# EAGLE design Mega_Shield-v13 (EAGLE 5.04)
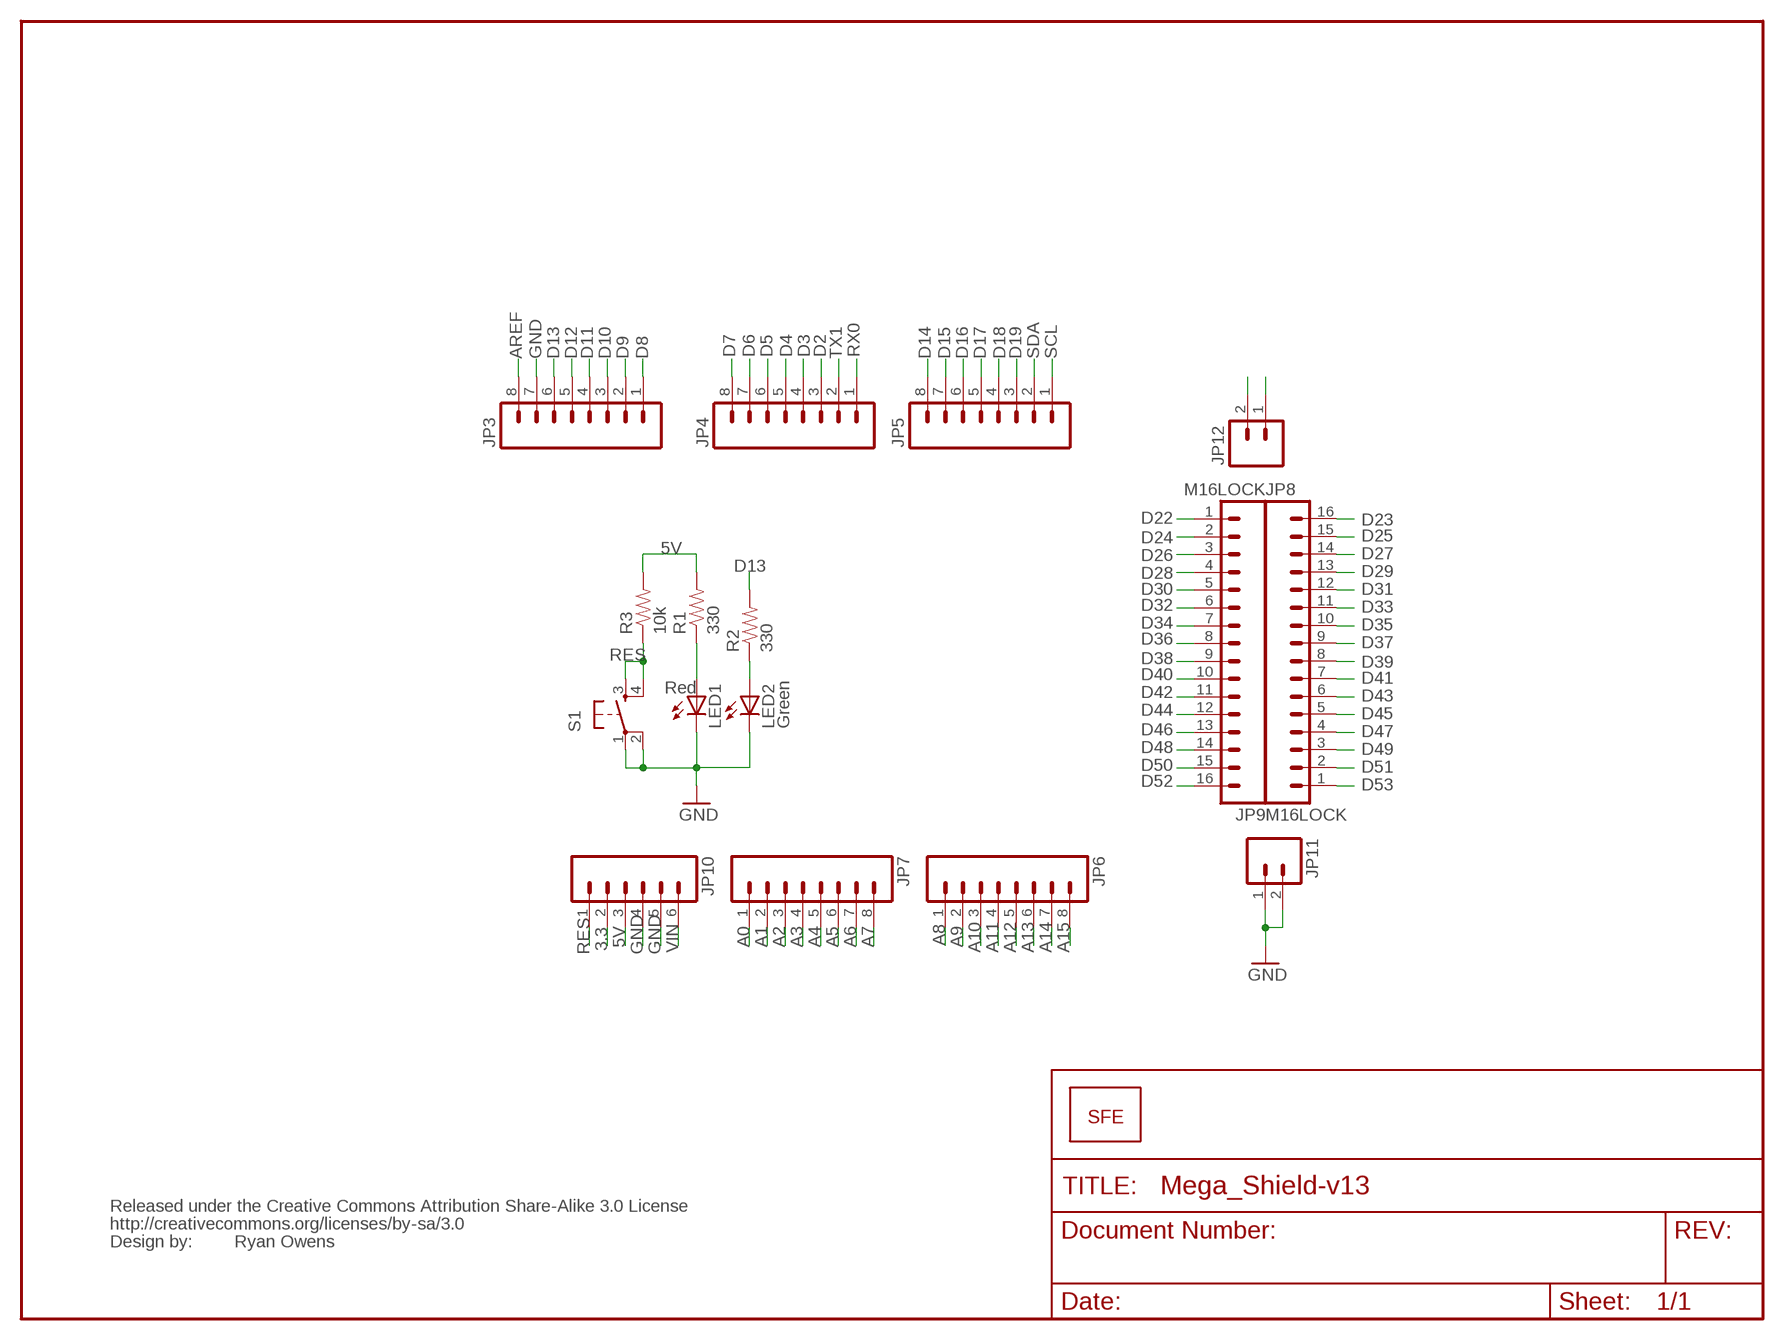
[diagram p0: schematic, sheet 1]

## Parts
JP3  M08LOCK  [1X08_LOCK]
JP4  M08LOCK  [1X08_LOCK]
JP5  M08LOCK  [1X08_LOCK]
JP6  M08LOCK  [1X08_LOCK]
JP7  M08LOCK  [1X08_LOCK]
JP8  M16LOCK  [1X16_LOCK]
JP9  M16LOCK  [1X16_LOCK]
JP10  M06LOCK  [1X06_LOCK]
JP11  M02LOCK  [1X02_LOCK]
JP12  M02LOCK  [1X02_LOCK]
LED1  Red  LED5MM  [LED5MM]
LED2  Green  LED5MM  [LED5MM]
R1  330  RESISTORPTH1  [AXIAL-0.3]
R2  330  RESISTORPTH1  [AXIAL-0.3]
R3  10k  RESISTORPTH1  [AXIAL-0.3]
S1  TAC_SWITCHPTH  [TACTILE-PTH]
U$1  LOGO-SFENEW  [SFE-NEW-WEBLOGO]
U$2  CREATIVE_COMMONS  [CREATIVE_COMMONS]

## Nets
3.3: JP10.2
5V: JP10.3 R1.P$2 R3.P$2
5V@1: JP12.1 JP12.2
A0: JP7.1
A1: JP7.2
A2: JP7.3
A3: JP7.4
A4: JP7.5
A5: JP7.6
A6: JP7.7
A7: JP7.8
A8: JP6.1
A9: JP6.2
A10: JP6.3
A11: JP6.4
A12: JP6.5
A13: JP6.6
A14: JP6.7
A15: JP6.8
AREF: JP3.8
D2: JP4.3
D3: JP4.4
D4: JP4.5
D5: JP4.6
D6: JP4.7
D7: JP4.8
D8: JP3.1
D9: JP3.2
D10: JP3.3
D11: JP3.4
D12: JP3.5
D13: JP3.6 R2.P$2
D14: JP5.8
D15: JP5.7
D16: JP5.6
D17: JP5.5
D18: JP5.4
D19: JP5.3
D22: JP9.1
D23: JP8.16
D24: JP9.2
D25: JP8.15
D26: JP9.3
D27: JP8.14
D28: JP9.4
D29: JP8.13
D30: JP9.5
D31: JP8.12
D32: JP9.6
D33: JP8.11
D34: JP9.7
D35: JP8.10
D36: JP9.8
D37: JP8.9
D38: JP9.9
D39: JP8.8
D40: JP9.10
D41: JP8.7
D42: JP9.11
D43: JP8.6
D44: JP9.12
D45: JP8.5
D46: JP9.13
D47: JP8.4
D48: JP9.14
D49: JP8.3
D50: JP9.15
D51: JP8.2
D52: JP9.16
D53: JP8.1
GND: JP3.7 JP10.4 JP10.5 JP11.1 JP11.2 LED1.K(C) LED2.K(C) S1.1 S1.2
N$126: LED1.A R1.P$1
N$127: LED2.A R2.P$1
RES: JP10.1 R3.P$1 S1.3 S1.4
RX0: JP4.1
SCL: JP5.1
SDA: JP5.2
TX1: JP4.2
VIN: JP10.6

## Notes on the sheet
- Ryan Owens

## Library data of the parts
JP3-JP7 = SparkFun:M08: Header 8 Standard 8-pin 0.1" header. Use with straight break away headers (SKU : PRT-00116), right angle break away headers (PRT-00553), swiss pins (PRT-00743), machine pins (PRT-00117), and female headers (PRT-00115).
JP8 JP9 = SparkFun:M16
JP10 = SparkFun:M06: Header 6 Standard 6-pin 0.1" header. Use with straight break away headers (SKU : PRT-00116), right angle break away headers (PRT-00553), swiss pins (PRT-00743), machine pins (PRT-00117), and female headers (PRT-00115). Molex polarized connector foot print use with SKU : PRT-08094 with associated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
JP11 JP12 = SparkFun:M02: Header 2
LED1 LED2 = SparkFun:LED: LEDs
R1-R3 = SparkFun:RESISTOR: Resistor
S1 = SparkFun:TAC_SWITCH: Momentary Switch Button commonly used for reset or general input. Spark Fun Electronics SKU : COM-00097
U$1 = SparkFun:LOGO-SFE: Spark Fun Electronics PCB Logo
U$2 = SparkFun:CREATIVE_COMMONS

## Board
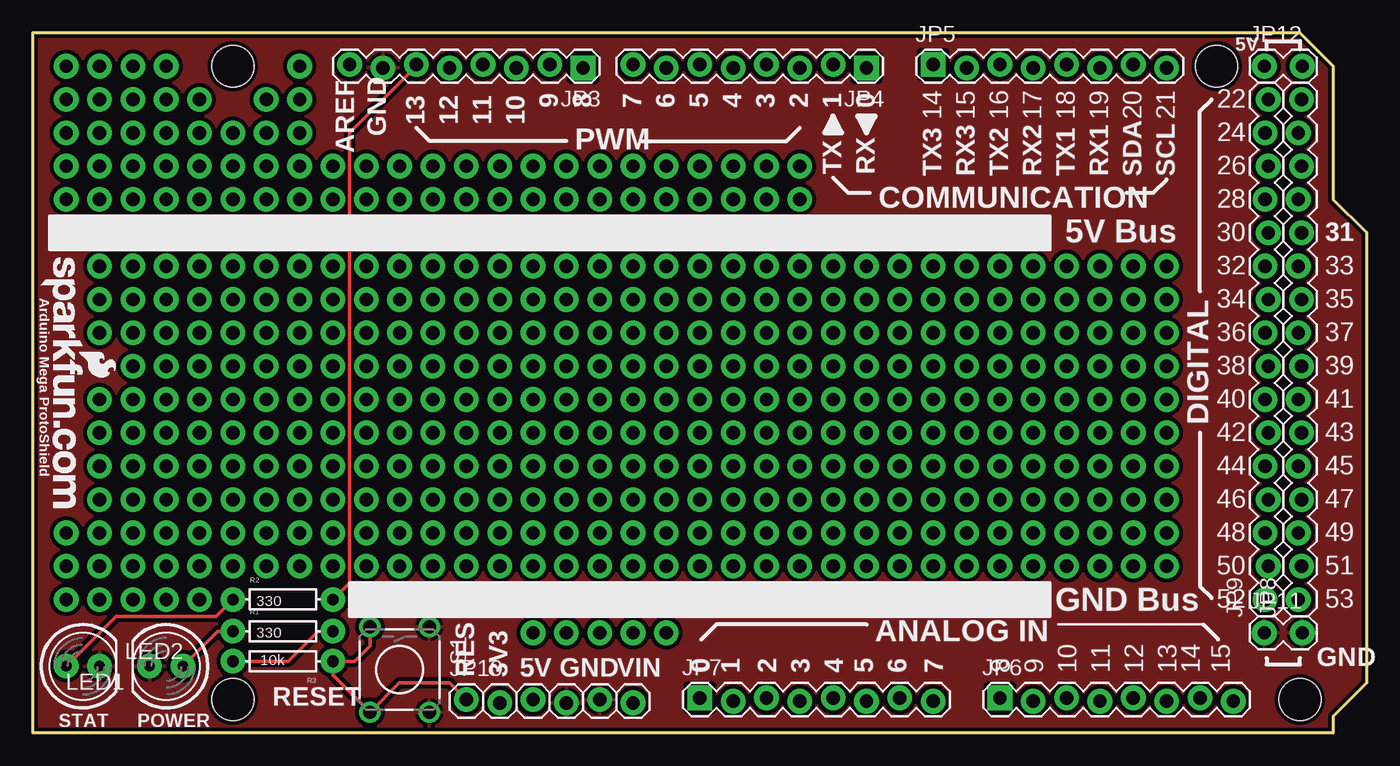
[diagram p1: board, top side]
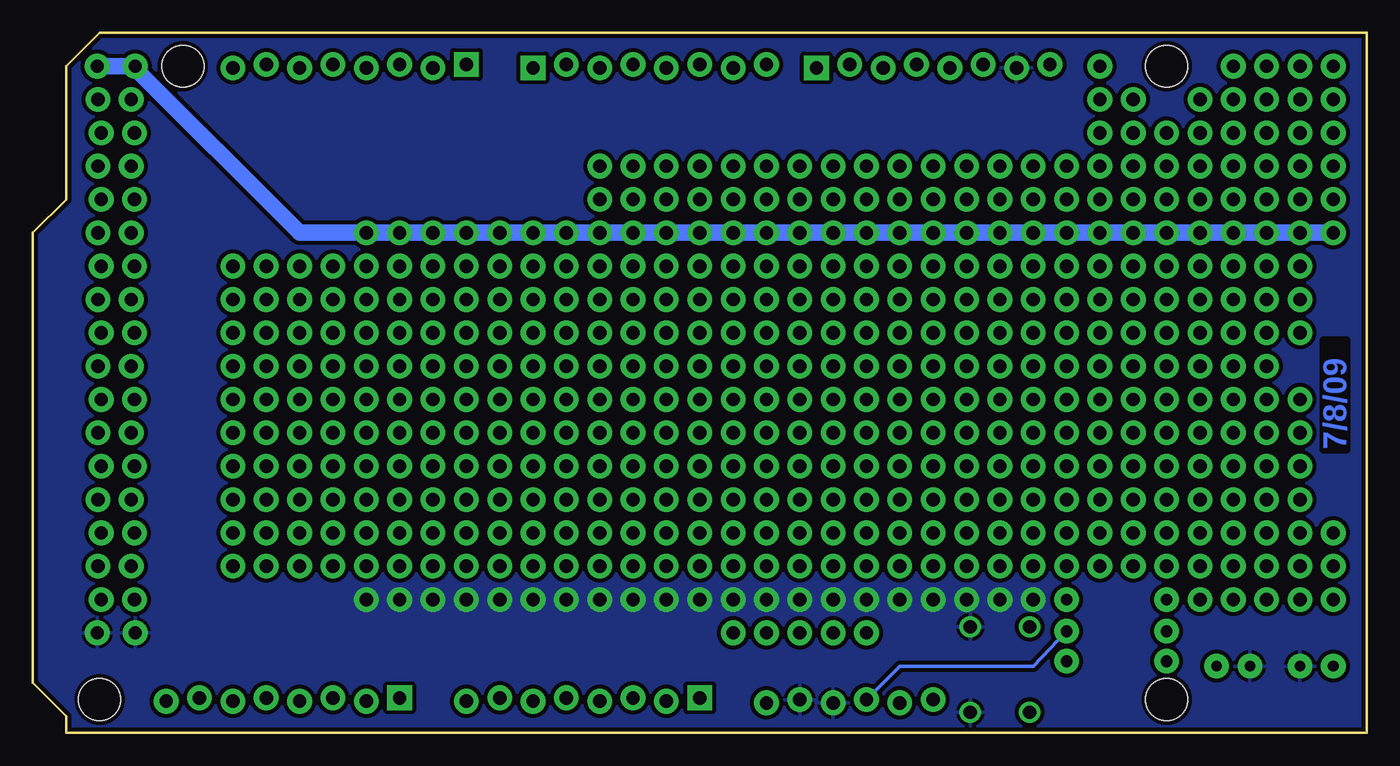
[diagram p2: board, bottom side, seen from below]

Size 101.6 x 53.34 mm. Coordinates in mm from the lower left corner, seen from the top.
Outline: 0,0 99.06,0 99.06,1.27 101.6,3.81 101.6,38.1 99.06,40.64 99.06,50.8 96.52,53.34 0,53.34 0,0
Copper layers (1*16): Top 0.035mm / dielectric 1.5mm / Bottom 0.035mm
Design rules "SparkFun": minimum track width 8mil, minimum drill 20mil, track to track 8mil, track to pad 8mil, pad to pad 8mil, via to via 8mil, smd to smd 8mil, copper to edge 10mil, drill to drill 8mil, minimum pad ring 12mil, minimum via ring 10mil, stop-mask expansion 4mil, vias tented up to drill 25mil, thermal gap 10mil
Holes 3.2 mm at 15.24,50.8 15.24,2.54 90.17,50.8 96.52,2.54

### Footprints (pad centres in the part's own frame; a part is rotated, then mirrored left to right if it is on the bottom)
1X08_LOCK = drill 1.016 pad 1.88 square: 1 0,0.127 | drill 1.016 pad 1.88 round: 2 2.54,-0.127; 3 5.08,0.127; 4 7.62,-0.127; 5 10.16,0.127; 6 12.7,-0.127; 7 15.24,0.127; 8 17.78,-0.127
1X16_LOCK = drill 1.016 pad 1.88 round: 1 0,0.127; 2 2.54,-0.127; 3 5.08,0.127; 4 7.62,-0.127; 5 10.16,0.127; 6 12.7,-0.127; 7 15.24,0.127; 8 17.78,-0.127; 9 20.32,0.127; 10 22.86,-0.127; 11 25.4,0.127; 12 27.94,-0.127; 13 30.48,0.127; 14 33.02,-0.127; 15 35.56,0.127; 16 38.1,-0.127
1X06_LOCK = drill 1.016 pad 1.88 round: 1 0,0; 2 2.54,-0.254; 3 5.08,0; 4 7.62,-0.254; 5 10.16,0; 6 12.7,-0.254
1X02_LOCK = drill 1.016 pad 1.88 round: 1 -0.178,0; 2 2.718,0
LED5MM = drill 0.813 pad 1.88 round: A -1.27,0; K 1.27,0
AXIAL-0.3 = drill 0.9 pad 1.88 round: P$1 -3.81,0; P$2 3.81,0
TACTILE-PTH = drill 1.016 round: 1 -3.251,2.261; 2 3.251,2.261; 3 -3.251,-2.261; 4 3.251,-2.261

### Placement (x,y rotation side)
JP3  41.91,50.8 180 top
JP4  63.5,50.8 180 top
JP5  68.58,50.8 0 top
JP6  73.66,2.54 0 top
JP7  50.8,2.54 0 top
JP8  96.52,10.16 90 top
JP9  93.98,10.16 90 top
JP10  33.02,2.54 0 top
JP11  93.98,7.62 0 top
JP12  93.98,50.8 0 top
LED1  10.16,5.08 180 top
LED2  3.81,5.08 0 top
R1  19.05,7.75 0 top
R2  19.05,10.16 0 top
R3  19.05,5.46 180 top
S1  27.94,4.83 270 top
U$1  0.64,36.2 270 top
U$2  not placed on the board

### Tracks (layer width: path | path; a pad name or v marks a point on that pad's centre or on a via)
3.3
  Top 0.203: JP10.2 35.56,2.54 JP10.2
5V
  Top 0.254: R3.P$2 19.43,5.46 21.72,7.75 R1.P$2
  Bottom 0.254: R1.P$2 25.4,5.08 35.56,5.08 JP10.3
5V@1  (via drill 1.02 pad 1.88)
  Bottom 1.27: v2.54,38.1 v5.08,38.1 v7.62,38.1 v10.16,38.1 v12.7,38.1 v15.24,38.1 v17.78,38.1 v20.32,38.1 v22.86,38.1 v25.4,38.1 v27.94,38.1 v30.48,38.1 v33.02,38.1 v35.56,38.1 v38.1,38.1 v40.64,38.1 v43.18,38.1 v45.72,38.1 v48.26,38.1 v50.8,38.1 v53.34,38.1 v55.88,38.1 v58.42,38.1 v60.96,38.1 v63.5,38.1 v66.04,38.1 v68.58,38.1 v71.12,38.1 v73.66,38.1 v76.2,38.1 81.1,38.1 81.28,38.1 93.98,50.8 JP12.1 96.52,50.8 JP12.2
A0
  Top 0.203: JP7.1 50.8,2.54
A1
  Top 0.203: JP7.2 53.34,2.54 JP7.2
A2
  Top 0.203: JP7.3 55.88,2.54
A3
  Top 0.203: JP7.4 58.42,2.54 JP7.4
A4
  Top 0.203: JP7.5 60.96,2.54
A5
  Top 0.203: JP7.6 63.5,2.54 JP7.6
A6
  Top 0.203: JP7.7 66.04,2.54
A7
  Top 0.203: JP7.8 68.58,2.54 JP7.8
A8
  Top 0.203: JP6.1 73.66,2.54
A9
  Top 0.203: JP6.2 76.2,2.54 JP6.2
A10
  Top 0.203: JP6.3 78.74,2.54
A11
  Top 0.203: JP6.4 81.28,2.54 JP6.4
A12
  Top 0.203: JP6.5 83.82,2.54
A13
  Top 0.203: JP6.6 86.36,2.54 JP6.6
A14
  Top 0.203: JP6.7 88.9,2.54
A15
  Top 0.203: JP6.8 91.44,2.54 JP6.8
AREF
  Top 0.203: JP3.8 24.13,50.8 JP3.8
D2
  Top 0.203: JP4.3 58.42,50.8
D3
  Top 0.203: JP4.4 55.88,50.8 JP4.4
D4
  Top 0.203: JP4.5 53.34,50.8
D5
  Top 0.203: JP4.6 50.8,50.8 JP4.6
D6
  Top 0.203: JP4.7 48.26,50.8
D7
  Top 0.203: JP4.8 45.72,50.8 JP4.8
D8
  Top 0.203: JP3.1 41.91,50.8
D9
  Top 0.203: JP3.2 39.37,50.8 JP3.2
D10
  Top 0.203: JP3.3 36.83,50.8
D11
  Top 0.203: JP3.4 34.29,50.8 JP3.4
D12
  Top 0.203: JP3.5 31.75,50.8
D13
  Top 0.254: R2.P$2 24.13,11.43 24.13,12.7 24.13,45.72 29.21,50.8 JP3.6
D14
  Top 0.203: JP5.8 86.36,50.8
D15
  Top 0.203: JP5.7 83.82,50.8 JP5.7
D16
  Top 0.203: JP5.6 81.28,50.8
D17
  Top 0.203: JP5.5 78.74,50.8 JP5.5
D18
  Top 0.203: JP5.4 76.2,50.8
D19
  Top 0.203: JP5.3 73.66,50.8 JP5.3
GND  (via drill 1.02 pad 1.88)
  other vias: 76.2,10.16 73.66,10.16 71.12,10.16 68.58,10.16 66.04,10.16 63.5,10.16 60.96,10.16 58.42,10.16 55.88,10.16 53.34,10.16 50.8,10.16 48.26,10.16 45.72,10.16 43.18,10.16 40.64,10.16 38.1,10.16 35.56,10.16 33.02,10.16 25.4,10.16 27.94,10.16 30.48,10.16
  pour Bottom (isolate 0.305): 0,0 99.06,0 99.06,1.27 101.6,3.81 101.6,38.1 99.06,40.64 99.06,50.8 96.52,53.34 0,53.34 0,2.54
  pour Top (isolate 0.305): 0,0 99.06,0 99.06,1.27 101.6,3.81 101.6,38.1 99.06,40.64 99.06,50.8 96.52,53.34 0,53.34 0,2.54
N$1  (via drill 1.02 pad 1.88)
  other vias: 27.94,12.7
N$2  (via drill 1.02 pad 1.88)
  other vias: 86.36,35.56
N$3  (via drill 1.02 pad 1.88)
  other vias: 86.36,33.02
N$4  (via drill 1.02 pad 1.88)
  other vias: 86.36,30.48
N$5  (via drill 1.02 pad 1.88)
  other vias: 86.36,27.94
N$6  (via drill 1.02 pad 1.88)
  other vias: 86.36,25.4
N$7  (via drill 1.02 pad 1.88)
  other vias: 86.36,22.86
N$8  (via drill 1.02 pad 1.88)
  other vias: 86.36,20.32
N$9  (via drill 1.02 pad 1.88)
  other vias: 86.36,17.78
N$10  (via drill 1.02 pad 1.88)
  other vias: 86.36,15.24
N$11  (via drill 1.02 pad 1.88)
  other vias: 86.36,12.7
N$12  (via drill 1.02 pad 1.88)
  other vias: 30.48,12.7
N$13  (via drill 1.02 pad 1.88)
  other vias: 2.54,10.16
N$14  (via drill 1.02 pad 1.88)
  other vias: 83.82,35.56
N$15  (via drill 1.02 pad 1.88)
  other vias: 83.82,33.02
N$16  (via drill 1.02 pad 1.88)
  other vias: 83.82,30.48
N$17  (via drill 1.02 pad 1.88)
  other vias: 83.82,27.94
N$18  (via drill 1.02 pad 1.88)
  other vias: 83.82,25.4
N$19  (via drill 1.02 pad 1.88)
  other vias: 83.82,22.86
N$20  (via drill 1.02 pad 1.88)
  other vias: 83.82,20.32
N$21  (via drill 1.02 pad 1.88)
  other vias: 83.82,17.78
N$22  (via drill 1.02 pad 1.88)
  other vias: 83.82,15.24
N$23  (via drill 1.02 pad 1.88)
  other vias: 83.82,12.7
N$24  (via drill 1.02 pad 1.88)
  other vias: 5.08,10.16
N$25  (via drill 1.02 pad 1.88)
  other vias: 7.62,10.16
N$26  (via drill 1.02 pad 1.88)
  other vias: 81.28,12.7
N$27  (via drill 1.02 pad 1.88)
  other vias: 81.28,15.24
N$28  (via drill 1.02 pad 1.88)
  other vias: 81.28,17.78
N$29  (via drill 1.02 pad 1.88)
  other vias: 81.28,20.32
N$30  (via drill 1.02 pad 1.88)
  other vias: 81.28,22.86
N$31  (via drill 1.02 pad 1.88)
  other vias: 81.28,25.4
N$32  (via drill 1.02 pad 1.88)
  other vias: 81.28,27.94
N$33  (via drill 1.02 pad 1.88)
  other vias: 81.28,30.48
N$34  (via drill 1.02 pad 1.88)
  other vias: 81.28,33.02
N$35  (via drill 1.02 pad 1.88)
  other vias: 81.28,35.56
N$36  (via drill 1.02 pad 1.88)
  other vias: 10.16,10.16
N$37  (via drill 1.02 pad 1.88)
  other vias: 12.7,10.16
N$38  (via drill 1.02 pad 1.88)
  other vias: 78.74,35.56
N$39  (via drill 1.02 pad 1.88)
  other vias: 78.74,33.02
N$40  (via drill 1.02 pad 1.88)
  other vias: 78.74,30.48
N$41  (via drill 1.02 pad 1.88)
  other vias: 78.74,27.94
N$42  (via drill 1.02 pad 1.88)
  other vias: 78.74,25.4
N$43  (via drill 1.02 pad 1.88)
  other vias: 78.74,22.86
N$44  (via drill 1.02 pad 1.88)
  other vias: 78.74,20.32
N$45  (via drill 1.02 pad 1.88)
  other vias: 78.74,17.78
N$46  (via drill 1.02 pad 1.88)
  other vias: 78.74,15.24
N$47  (via drill 1.02 pad 1.88)
  other vias: 78.74,12.7
N$50  (via drill 1.02 pad 1.88)
  other vias: 76.2,12.7
N$51  (via drill 1.02 pad 1.88)
  other vias: 76.2,15.24
N$52  (via drill 1.02 pad 1.88)
  other vias: 76.2,17.78
N$53  (via drill 1.02 pad 1.88)
  other vias: 76.2,20.32
N$54  (via drill 1.02 pad 1.88)
  other vias: 76.2,22.86
N$55  (via drill 1.02 pad 1.88)
  other vias: 76.2,25.4
N$56  (via drill 1.02 pad 1.88)
  other vias: 76.2,27.94
N$57  (via drill 1.02 pad 1.88)
  other vias: 76.2,30.48
N$58  (via drill 1.02 pad 1.88)
  other vias: 76.2,33.02
N$59  (via drill 1.02 pad 1.88)
  other vias: 76.2,35.56
N$62  (via drill 1.02 pad 1.88)
  other vias: 73.66,35.56
N$63  (via drill 1.02 pad 1.88)
  other vias: 73.66,33.02
N$64  (via drill 1.02 pad 1.88)
  other vias: 73.66,30.48
N$65  (via drill 1.02 pad 1.88)
  other vias: 73.66,27.94
N$66  (via drill 1.02 pad 1.88)
  other vias: 73.66,25.4
N$67  (via drill 1.02 pad 1.88)
  other vias: 73.66,22.86
N$68  (via drill 1.02 pad 1.88)
  other vias: 73.66,20.32
N$69  (via drill 1.02 pad 1.88)
  other vias: 73.66,17.78
N$70  (via drill 1.02 pad 1.88)
  other vias: 73.66,15.24
N$71  (via drill 1.02 pad 1.88)
  other vias: 73.66,12.7
N$74  (via drill 1.02 pad 1.88)
  other vias: 71.12,12.7
N$75  (via drill 1.02 pad 1.88)
  other vias: 71.12,15.24
N$76  (via drill 1.02 pad 1.88)
  other vias: 71.12,17.78
N$77  (via drill 1.02 pad 1.88)
  other vias: 71.12,20.32
N$78  (via drill 1.02 pad 1.88)
  other vias: 71.12,22.86
N$79  (via drill 1.02 pad 1.88)
  other vias: 71.12,25.4
N$80  (via drill 1.02 pad 1.88)
  other vias: 71.12,27.94
N$81  (via drill 1.02 pad 1.88)
  other vias: 71.12,30.48
N$82  (via drill 1.02 pad 1.88)
  other vias: 71.12,33.02
N$83  (via drill 1.02 pad 1.88)
  other vias: 71.12,35.56
N$86  (via drill 1.02 pad 1.88)
  other vias: 68.58,35.56
N$87  (via drill 1.02 pad 1.88)
  other vias: 68.58,33.02
N$88  (via drill 1.02 pad 1.88)
  other vias: 68.58,30.48
N$89  (via drill 1.02 pad 1.88)
  other vias: 68.58,27.94
N$90  (via drill 1.02 pad 1.88)
  other vias: 68.58,25.4
N$91  (via drill 1.02 pad 1.88)
  other vias: 68.58,22.86
N$92  (via drill 1.02 pad 1.88)
  other vias: 68.58,20.32
N$93  (via drill 1.02 pad 1.88)
  other vias: 68.58,17.78
N$94  (via drill 1.02 pad 1.88)
  other vias: 68.58,15.24
N$95  (via drill 1.02 pad 1.88)
  other vias: 68.58,12.7
N$98  (via drill 1.02 pad 1.88)
  other vias: 66.04,12.7
N$99  (via drill 1.02 pad 1.88)
  other vias: 66.04,15.24
N$100  (via drill 1.02 pad 1.88)
  other vias: 66.04,17.78
N$101  (via drill 1.02 pad 1.88)
  other vias: 66.04,20.32
N$102  (via drill 1.02 pad 1.88)
  other vias: 66.04,22.86
N$103  (via drill 1.02 pad 1.88)
  other vias: 66.04,25.4
N$104  (via drill 1.02 pad 1.88)
  other vias: 66.04,27.94
N$105  (via drill 1.02 pad 1.88)
  other vias: 66.04,30.48
N$106  (via drill 1.02 pad 1.88)
  other vias: 66.04,33.02
N$107  (via drill 1.02 pad 1.88)
  other vias: 66.04,35.56
N$110  (via drill 1.02 pad 1.88)
  other vias: 63.5,35.56
N$111  (via drill 1.02 pad 1.88)
  other vias: 63.5,33.02
N$112  (via drill 1.02 pad 1.88)
  other vias: 63.5,30.48
N$113  (via drill 1.02 pad 1.88)
  other vias: 63.5,27.94
N$114  (via drill 1.02 pad 1.88)
  other vias: 63.5,25.4
N$115  (via drill 1.02 pad 1.88)
  other vias: 63.5,22.86
N$116  (via drill 1.02 pad 1.88)
  other vias: 63.5,20.32
N$117  (via drill 1.02 pad 1.88)
  other vias: 63.5,17.78
N$118  (via drill 1.02 pad 1.88)
  other vias: 63.5,15.24
N$119  (via drill 1.02 pad 1.88)
  other vias: 63.5,12.7
N$122  (via drill 1.02 pad 1.88)
  other vias: 60.96,12.7
N$123  (via drill 1.02 pad 1.88)
  other vias: 60.96,15.24
N$124  (via drill 1.02 pad 1.88)
  other vias: 60.96,17.78
N$126
  Top 0.254: R1.P$1 14.1,7.75 LED1.A
N$127
  Top 0.254: R2.P$1 13.97,8.89 6.35,8.89 LED2.A
N$128  (via drill 1.02 pad 1.88)
  other vias: 60.96,20.32
N$129  (via drill 1.02 pad 1.88)
  other vias: 60.96,22.86
N$130  (via drill 1.02 pad 1.88)
  other vias: 60.96,25.4
N$131  (via drill 1.02 pad 1.88)
  other vias: 60.96,27.94
N$132  (via drill 1.02 pad 1.88)
  other vias: 60.96,30.48
N$133  (via drill 1.02 pad 1.88)
  other vias: 60.96,33.02
N$134  (via drill 1.02 pad 1.88)
  other vias: 60.96,35.56
N$136  (via drill 1.02 pad 1.88)
  other vias: 58.42,43.18
N$137  (via drill 1.02 pad 1.88)
  other vias: 58.42,40.64
N$139  (via drill 1.02 pad 1.88)
  other vias: 58.42,35.56
N$140  (via drill 1.02 pad 1.88)
  other vias: 58.42,33.02
N$141  (via drill 1.02 pad 1.88)
  other vias: 58.42,30.48
N$142  (via drill 1.02 pad 1.88)
  other vias: 58.42,27.94
N$143  (via drill 1.02 pad 1.88)
  other vias: 58.42,25.4
N$144  (via drill 1.02 pad 1.88)
  other vias: 58.42,22.86
N$145  (via drill 1.02 pad 1.88)
  other vias: 58.42,20.32
N$146  (via drill 1.02 pad 1.88)
  other vias: 58.42,17.78
N$147  (via drill 1.02 pad 1.88)
  other vias: 58.42,15.24
N$148  (via drill 1.02 pad 1.88)
  other vias: 58.42,12.7
N$151  (via drill 1.02 pad 1.88)
  other vias: 55.88,12.7
N$152  (via drill 1.02 pad 1.88)
  other vias: 55.88,15.24
N$153  (via drill 1.02 pad 1.88)
  other vias: 55.88,17.78
N$154  (via drill 1.02 pad 1.88)
  other vias: 55.88,20.32
N$155  (via drill 1.02 pad 1.88)
  other vias: 55.88,22.86
N$156  (via drill 1.02 pad 1.88)
  other vias: 55.88,25.4
N$157  (via drill 1.02 pad 1.88)
  other vias: 55.88,27.94
N$158  (via drill 1.02 pad 1.88)
  other vias: 55.88,30.48
N$159  (via drill 1.02 pad 1.88)
  other vias: 55.88,33.02
N$160  (via drill 1.02 pad 1.88)
  other vias: 55.88,35.56
N$162  (via drill 1.02 pad 1.88)
  other vias: 55.88,40.64
N$163  (via drill 1.02 pad 1.88)
  other vias: 55.88,43.18
N$164  (via drill 1.02 pad 1.88)
  other vias: 53.34,43.18
N$165  (via drill 1.02 pad 1.88)
  other vias: 53.34,40.64
N$167  (via drill 1.02 pad 1.88)
  other vias: 53.34,35.56
N$168  (via drill 1.02 pad 1.88)
  other vias: 53.34,33.02
N$169  (via drill 1.02 pad 1.88)
  other vias: 53.34,30.48
N$170  (via drill 1.02 pad 1.88)
  other vias: 53.34,27.94
N$171  (via drill 1.02 pad 1.88)
  other vias: 53.34,25.4
N$172  (via drill 1.02 pad 1.88)
  other vias: 53.34,22.86
N$173  (via drill 1.02 pad 1.88)
  other vias: 53.34,20.32
N$174  (via drill 1.02 pad 1.88)
  other vias: 53.34,17.78
N$175  (via drill 1.02 pad 1.88)
  other vias: 53.34,15.24
N$176  (via drill 1.02 pad 1.88)
  other vias: 53.34,12.7
N$179  (via drill 1.02 pad 1.88)
  other vias: 50.8,12.7
N$180  (via drill 1.02 pad 1.88)
  other vias: 50.8,15.24
N$181  (via drill 1.02 pad 1.88)
  other vias: 50.8,17.78
N$182  (via drill 1.02 pad 1.88)
  other vias: 50.8,20.32
N$183  (via drill 1.02 pad 1.88)
  other vias: 50.8,22.86
N$184  (via drill 1.02 pad 1.88)
  other vias: 50.8,25.4
N$185  (via drill 1.02 pad 1.88)
  other vias: 50.8,27.94
N$186  (via drill 1.02 pad 1.88)
  other vias: 50.8,30.48
N$187  (via drill 1.02 pad 1.88)
  other vias: 50.8,33.02
N$188  (via drill 1.02 pad 1.88)
  other vias: 50.8,35.56
N$190  (via drill 1.02 pad 1.88)
  other vias: 50.8,40.64
N$191  (via drill 1.02 pad 1.88)
  other vias: 50.8,43.18
N$192  (via drill 1.02 pad 1.88)
  other vias: 48.26,43.18
N$193  (via drill 1.02 pad 1.88)
  other vias: 48.26,40.64
N$195  (via drill 1.02 pad 1.88)
  other vias: 48.26,35.56
N$196  (via drill 1.02 pad 1.88)
  other vias: 48.26,33.02
N$197  (via drill 1.02 pad 1.88)
  other vias: 48.26,30.48
N$198  (via drill 1.02 pad 1.88)
  other vias: 48.26,27.94
N$199  (via drill 1.02 pad 1.88)
  other vias: 48.26,25.4
N$200  (via drill 1.02 pad 1.88)
  other vias: 48.26,22.86
N$201  (via drill 1.02 pad 1.88)
  other vias: 48.26,20.32
N$202  (via drill 1.02 pad 1.88)
  other vias: 48.26,17.78
N$203  (via drill 1.02 pad 1.88)
  other vias: 48.26,15.24
N$204  (via drill 1.02 pad 1.88)
  other vias: 48.26,12.7
N$207  (via drill 1.02 pad 1.88)
  other vias: 45.72,12.7
N$208  (via drill 1.02 pad 1.88)
  other vias: 45.72,15.24
N$209  (via drill 1.02 pad 1.88)
  other vias: 45.72,17.78
N$210  (via drill 1.02 pad 1.88)
  other vias: 45.72,20.32
N$211  (via drill 1.02 pad 1.88)
  other vias: 45.72,22.86
N$212  (via drill 1.02 pad 1.88)
  other vias: 45.72,25.4
N$213  (via drill 1.02 pad 1.88)
  other vias: 45.72,27.94
N$214  (via drill 1.02 pad 1.88)
  other vias: 45.72,30.48
N$215  (via drill 1.02 pad 1.88)
  other vias: 45.72,33.02
N$216  (via drill 1.02 pad 1.88)
  other vias: 45.72,35.56
N$218  (via drill 1.02 pad 1.88)
  other vias: 45.72,40.64
N$219  (via drill 1.02 pad 1.88)
  other vias: 45.72,43.18
N$220  (via drill 1.02 pad 1.88)
  other vias: 43.18,43.18
N$221  (via drill 1.02 pad 1.88)
  other vias: 43.18,40.64
N$223  (via drill 1.02 pad 1.88)
  other vias: 43.18,35.56
N$224  (via drill 1.02 pad 1.88)
  other vias: 43.18,33.02
N$225  (via drill 1.02 pad 1.88)
  other vias: 43.18,30.48
N$226  (via drill 1.02 pad 1.88)
  other vias: 43.18,27.94
N$227  (via drill 1.02 pad 1.88)
  other vias: 43.18,25.4
N$228  (via drill 1.02 pad 1.88)
  other vias: 43.18,22.86
N$229  (via drill 1.02 pad 1.88)
  other vias: 43.18,20.32
N$230  (via drill 1.02 pad 1.88)
  other vias: 43.18,17.78
N$231  (via drill 1.02 pad 1.88)
  other vias: 43.18,15.24
N$232  (via drill 1.02 pad 1.88)
  other vias: 43.18,12.7
N$235  (via drill 1.02 pad 1.88)
  other vias: 40.64,12.7
N$236  (via drill 1.02 pad 1.88)
  other vias: 40.64,15.24
N$237  (via drill 1.02 pad 1.88)
  other vias: 40.64,17.78
N$238  (via drill 1.02 pad 1.88)
  other vias: 40.64,20.32
N$239  (via drill 1.02 pad 1.88)
  other vias: 40.64,22.86
N$240  (via drill 1.02 pad 1.88)
  other vias: 40.64,25.4
N$241  (via drill 1.02 pad 1.88)
  other vias: 40.64,27.94
N$242  (via drill 1.02 pad 1.88)
  other vias: 40.64,30.48
N$243  (via drill 1.02 pad 1.88)
  other vias: 40.64,33.02
N$244  (via drill 1.02 pad 1.88)
  other vias: 40.64,35.56
N$246  (via drill 1.02 pad 1.88)
  other vias: 40.64,40.64
N$247  (via drill 1.02 pad 1.88)
  other vias: 40.64,43.18
N$248  (via drill 1.02 pad 1.88)
  other vias: 38.1,43.18
N$249  (via drill 1.02 pad 1.88)
  other vias: 38.1,40.64
N$251  (via drill 1.02 pad 1.88)
  other vias: 38.1,35.56
N$252  (via drill 1.02 pad 1.88)
  other vias: 38.1,33.02
N$253  (via drill 1.02 pad 1.88)
  other vias: 38.1,30.48
N$254  (via drill 1.02 pad 1.88)
  other vias: 38.1,27.94
N$255  (via drill 1.02 pad 1.88)
  other vias: 38.1,25.4
N$256  (via drill 1.02 pad 1.88)
  other vias: 38.1,22.86
N$257  (via drill 1.02 pad 1.88)
  other vias: 38.1,20.32
N$258  (via drill 1.02 pad 1.88)
  other vias: 38.1,17.78
N$259  (via drill 1.02 pad 1.88)
  other vias: 38.1,15.24
N$260  (via drill 1.02 pad 1.88)
  other vias: 38.1,12.7
N$263  (via drill 1.02 pad 1.88)
  other vias: 35.56,12.7
N$264  (via drill 1.02 pad 1.88)
  other vias: 35.56,15.24
N$265  (via drill 1.02 pad 1.88)
  other vias: 35.56,17.78
N$266  (via drill 1.02 pad 1.88)
  other vias: 35.56,20.32
N$267  (via drill 1.02 pad 1.88)
  other vias: 35.56,22.86
N$268  (via drill 1.02 pad 1.88)
  other vias: 35.56,25.4
N$269  (via drill 1.02 pad 1.88)
  other vias: 35.56,27.94
N$270  (via drill 1.02 pad 1.88)
  other vias: 35.56,30.48
N$271  (via drill 1.02 pad 1.88)
  other vias: 35.56,33.02
N$272  (via drill 1.02 pad 1.88)
  other vias: 35.56,35.56
N$274  (via drill 1.02 pad 1.88)
  other vias: 35.56,40.64
N$275  (via drill 1.02 pad 1.88)
  other vias: 35.56,43.18
N$276  (via drill 1.02 pad 1.88)
  other vias: 33.02,43.18
N$277  (via drill 1.02 pad 1.88)
  other vias: 33.02,40.64
N$279  (via drill 1.02 pad 1.88)
  other vias: 33.02,35.56
N$280  (via drill 1.02 pad 1.88)
  other vias: 33.02,33.02
N$281  (via drill 1.02 pad 1.88)
  other vias: 33.02,30.48
N$282  (via drill 1.02 pad 1.88)
  other vias: 33.02,27.94
N$283  (via drill 1.02 pad 1.88)
  other vias: 33.02,22.86
N$284  (via drill 1.02 pad 1.88)
  other vias: 33.02,25.4
N$285  (via drill 1.02 pad 1.88)
  other vias: 33.02,20.32
N$286  (via drill 1.02 pad 1.88)
  other vias: 33.02,17.78
N$287  (via drill 1.02 pad 1.88)
  other vias: 33.02,15.24
N$288  (via drill 1.02 pad 1.88)
  other vias: 33.02,12.7
N$292  (via drill 1.02 pad 1.88)
  other vias: 30.48,15.24
N$293  (via drill 1.02 pad 1.88)
  other vias: 30.48,17.78
N$294  (via drill 1.02 pad 1.88)
  other vias: 30.48,20.32
N$295  (via drill 1.02 pad 1.88)
  other vias: 30.48,22.86
N$296  (via drill 1.02 pad 1.88)
  other vias: 30.48,25.4
N$297  (via drill 1.02 pad 1.88)
  other vias: 30.48,27.94
N$298  (via drill 1.02 pad 1.88)
  other vias: 30.48,30.48
N$299  (via drill 1.02 pad 1.88)
  other vias: 30.48,33.02
N$300  (via drill 1.02 pad 1.88)
  other vias: 30.48,35.56
N$302  (via drill 1.02 pad 1.88)
  other vias: 30.48,40.64
N$303  (via drill 1.02 pad 1.88)
  other vias: 30.48,43.18
N$304  (via drill 1.02 pad 1.88)
  other vias: 27.94,43.18
N$305  (via drill 1.02 pad 1.88)
  other vias: 27.94,40.64
N$307  (via drill 1.02 pad 1.88)
  other vias: 27.94,35.56
N$308  (via drill 1.02 pad 1.88)
  other vias: 27.94,33.02
N$309  (via drill 1.02 pad 1.88)
  other vias: 27.94,30.48
N$310  (via drill 1.02 pad 1.88)
  other vias: 27.94,27.94
N$311  (via drill 1.02 pad 1.88)
  other vias: 27.94,25.4
N$312  (via drill 1.02 pad 1.88)
  other vias: 27.94,20.32
N$313  (via drill 1.02 pad 1.88)
  other vias: 27.94,15.24
N$319  (via drill 1.02 pad 1.88)
  other vias: 38.1,7.62
N$320  (via drill 1.02 pad 1.88)
  other vias: 40.64,7.62
N$321  (via drill 1.02 pad 1.88)
  other vias: 43.18,7.62
N$322  (via drill 1.02 pad 1.88)
  other vias: 48.26,7.62
N$323  (via drill 1.02 pad 1.88)
  other vias: 45.72,7.62
N$324  (via drill 1.02 pad 1.88)
  other vias: 27.94,17.78
N$325  (via drill 1.02 pad 1.88)
  other vias: 27.94,22.86
N$326  (via drill 1.02 pad 1.88)
  other vias: 25.4,43.18
N$327  (via drill 1.02 pad 1.88)
  other vias: 25.4,40.64
N$329  (via drill 1.02 pad 1.88)
  other vias: 25.4,35.56
N$330  (via drill 1.02 pad 1.88)
  other vias: 25.4,33.02
N$331  (via drill 1.02 pad 1.88)
  other vias: 25.4,30.48
N$332  (via drill 1.02 pad 1.88)
  other vias: 25.4,27.94
N$333  (via drill 1.02 pad 1.88)
  other vias: 25.4,25.4
N$334  (via drill 1.02 pad 1.88)
  other vias: 25.4,22.86
N$335  (via drill 1.02 pad 1.88)
  other vias: 25.4,20.32
N$336  (via drill 1.02 pad 1.88)
  other vias: 25.4,17.78
N$337  (via drill 1.02 pad 1.88)
  other vias: 25.4,15.24
N$338  (via drill 1.02 pad 1.88)
  other vias: 25.4,12.7
N$343  (via drill 1.02 pad 1.88)
  other vias: 22.86,12.7
N$344  (via drill 1.02 pad 1.88)
  other vias: 22.86,15.24
N$345  (via drill 1.02 pad 1.88)
  other vias: 22.86,17.78
N$346  (via drill 1.02 pad 1.88)
  other vias: 22.86,20.32
N$347  (via drill 1.02 pad 1.88)
  other vias: 22.86,22.86
N$348  (via drill 1.02 pad 1.88)
  other vias: 22.86,25.4
N$349  (via drill 1.02 pad 1.88)
  other vias: 22.86,27.94
N$350  (via drill 1.02 pad 1.88)
  other vias: 22.86,30.48
N$351  (via drill 1.02 pad 1.88)
  other vias: 22.86,33.02
N$352  (via drill 1.02 pad 1.88)
  other vias: 22.86,35.56
N$354  (via drill 1.02 pad 1.88)
  other vias: 22.86,40.64
N$355  (via drill 1.02 pad 1.88)
  other vias: 22.86,43.18
N$356  (via drill 1.02 pad 1.88)
  other vias: 20.32,45.72
N$357  (via drill 1.02 pad 1.88)
  other vias: 20.32,48.26
N$358  (via drill 1.02 pad 1.88)
  other vias: 20.32,50.8
N$359  (via drill 1.02 pad 1.88)
  other vias: 20.32,43.18
N$360  (via drill 1.02 pad 1.88)
  other vias: 20.32,40.64
N$362  (via drill 1.02 pad 1.88)
  other vias: 20.32,35.56
N$363  (via drill 1.02 pad 1.88)
  other vias: 20.32,33.02
N$364  (via drill 1.02 pad 1.88)
  other vias: 20.32,30.48
N$365  (via drill 1.02 pad 1.88)
  other vias: 20.32,27.94
N$366  (via drill 1.02 pad 1.88)
  other vias: 20.32,22.86
N$367  (via drill 1.02 pad 1.88)
  other vias: 20.32,25.4
N$368  (via drill 1.02 pad 1.88)
  other vias: 20.32,20.32
N$369  (via drill 1.02 pad 1.88)
  other vias: 20.32,17.78
N$370  (via drill 1.02 pad 1.88)
  other vias: 20.32,15.24
N$371  (via drill 1.02 pad 1.88)
  other vias: 20.32,12.7
N$376  (via drill 1.02 pad 1.88)
  other vias: 17.78,12.7
N$377  (via drill 1.02 pad 1.88)
  other vias: 17.78,15.24
N$378  (via drill 1.02 pad 1.88)
  other vias: 17.78,17.78
N$379  (via drill 1.02 pad 1.88)
  other vias: 17.78,20.32
N$380  (via drill 1.02 pad 1.88)
  other vias: 17.78,22.86
N$381  (via drill 1.02 pad 1.88)
  other vias: 17.78,25.4
N$382  (via drill 1.02 pad 1.88)
  other vias: 17.78,27.94
N$383  (via drill 1.02 pad 1.88)
  other vias: 17.78,30.48
N$384  (via drill 1.02 pad 1.88)
  other vias: 17.78,33.02
N$385  (via drill 1.02 pad 1.88)
  other vias: 17.78,35.56
N$387  (via drill 1.02 pad 1.88)
  other vias: 17.78,40.64
N$388  (via drill 1.02 pad 1.88)
  other vias: 17.78,43.18
N$389  (via drill 1.02 pad 1.88)
  other vias: 17.78,45.72
N$390  (via drill 1.02 pad 1.88)
  other vias: 15.24,45.72
N$391  (via drill 1.02 pad 1.88)
  other vias: 12.7,45.72
N$392  (via drill 1.02 pad 1.88)
  other vias: 10.16,45.72
N$393  (via drill 1.02 pad 1.88)
  other vias: 7.62,45.72
N$394  (via drill 1.02 pad 1.88)
  other vias: 5.08,45.72
N$395  (via drill 1.02 pad 1.88)
  other vias: 5.08,43.18
N$397  (via drill 1.02 pad 1.88)
  other vias: 5.08,40.64
N$398  (via drill 1.02 pad 1.88)
  other vias: 5.08,35.56
N$399  (via drill 1.02 pad 1.88)
  other vias: 5.08,33.02
N$400  (via drill 1.02 pad 1.88)
  other vias: 5.08,30.48
N$401  (via drill 1.02 pad 1.88)
  other vias: 7.62,30.48
N$402  (via drill 1.02 pad 1.88)
  other vias: 7.62,33.02
N$403  (via drill 1.02 pad 1.88)
  other vias: 7.62,35.56
N$405  (via drill 1.02 pad 1.88)
  other vias: 7.62,40.64
N$406  (via drill 1.02 pad 1.88)
  other vias: 7.62,43.18
N$407  (via drill 1.02 pad 1.88)
  other vias: 10.16,43.18
N$408  (via drill 1.02 pad 1.88)
  other vias: 10.16,40.64
N$410  (via drill 1.02 pad 1.88)
  other vias: 10.16,35.56
N$411  (via drill 1.02 pad 1.88)
  other vias: 10.16,33.02
N$412  (via drill 1.02 pad 1.88)
  other vias: 10.16,30.48
N$413  (via drill 1.02 pad 1.88)
  other vias: 12.7,30.48
N$414  (via drill 1.02 pad 1.88)
  other vias: 12.7,33.02
N$415  (via drill 1.02 pad 1.88)
  other vias: 12.7,35.56
N$417  (via drill 1.02 pad 1.88)
  other vias: 12.7,40.64
N$418  (via drill 1.02 pad 1.88)
  other vias: 12.7,43.18
N$419  (via drill 1.02 pad 1.88)
  other vias: 15.24,43.18
N$420  (via drill 1.02 pad 1.88)
  other vias: 15.24,40.64
N$422  (via drill 1.02 pad 1.88)
  other vias: 15.24,35.56
N$423  (via drill 1.02 pad 1.88)
  other vias: 15.24,33.02
N$424  (via drill 1.02 pad 1.88)
  other vias: 15.24,30.48
N$425  (via drill 1.02 pad 1.88)
  other vias: 15.24,27.94
N$426  (via drill 1.02 pad 1.88)
  other vias: 15.24,25.4
N$427  (via drill 1.02 pad 1.88)
  other vias: 15.24,22.86
N$428  (via drill 1.02 pad 1.88)
  other vias: 15.24,20.32
N$429  (via drill 1.02 pad 1.88)
  other vias: 15.24,17.78
N$430  (via drill 1.02 pad 1.88)
  other vias: 15.24,12.7
N$431  (via drill 1.02 pad 1.88)
  other vias: 15.24,15.24
N$436  (via drill 1.02 pad 1.88)
  other vias: 12.7,12.7
N$437  (via drill 1.02 pad 1.88)
  other vias: 12.7,15.24
N$438  (via drill 1.02 pad 1.88)
  other vias: 12.7,20.32
N$439  (via drill 1.02 pad 1.88)
  other vias: 12.7,17.78
N$440  (via drill 1.02 pad 1.88)
  other vias: 12.7,22.86
N$441  (via drill 1.02 pad 1.88)
  other vias: 12.7,25.4
N$442  (via drill 1.02 pad 1.88)
  other vias: 12.7,27.94
N$443  (via drill 1.02 pad 1.88)
  other vias: 10.16,27.94
N$444  (via drill 1.02 pad 1.88)
  other vias: 7.62,25.4
N$445  (via drill 1.02 pad 1.88)
  other vias: 10.16,25.4
N$446  (via drill 1.02 pad 1.88)
  other vias: 10.16,22.86
N$447  (via drill 1.02 pad 1.88)
  other vias: 7.62,22.86
N$448  (via drill 1.02 pad 1.88)
  other vias: 5.08,22.86
N$449  (via drill 1.02 pad 1.88)
  other vias: 5.08,20.32
N$450  (via drill 1.02 pad 1.88)
  other vias: 5.08,17.78
N$451  (via drill 1.02 pad 1.88)
  other vias: 5.08,15.24
N$452  (via drill 1.02 pad 1.88)
  other vias: 5.08,12.7
N$460  (via drill 1.02 pad 1.88)
  other vias: 10.16,12.7
N$461  (via drill 1.02 pad 1.88)
  other vias: 10.16,15.24
N$462  (via drill 1.02 pad 1.88)
  other vias: 10.16,17.78
N$463  (via drill 1.02 pad 1.88)
  other vias: 10.16,20.32
N$464  (via drill 1.02 pad 1.88)
  other vias: 7.62,20.32
N$465  (via drill 1.02 pad 1.88)
  other vias: 7.62,17.78
N$466  (via drill 1.02 pad 1.88)
  other vias: 7.62,12.7
N$467  (via drill 1.02 pad 1.88)
  other vias: 7.62,15.24
N$477  (via drill 1.02 pad 1.88)
  other vias: 12.7,48.26
N$478  (via drill 1.02 pad 1.88)
  other vias: 10.16,48.26
N$479  (via drill 1.02 pad 1.88)
  other vias: 7.62,48.26
N$480  (via drill 1.02 pad 1.88)
  other vias: 5.08,48.26
N$481  (via drill 1.02 pad 1.88)
  other vias: 5.08,50.8
N$482  (via drill 1.02 pad 1.88)
  other vias: 7.62,50.8
N$483  (via drill 1.02 pad 1.88)
  other vias: 10.16,50.8
N$484  (via drill 1.02 pad 1.88)
  other vias: 17.78,48.26
N$492  (via drill 1.02 pad 1.88)
  other vias: 2.54,12.7
N$493  (via drill 1.02 pad 1.88)
  other vias: 2.54,15.24
N$495  (via drill 1.02 pad 1.88)
  other vias: 2.54,43.18
N$496  (via drill 1.02 pad 1.88)
  other vias: 2.54,40.64
N$497  (via drill 1.02 pad 1.88)
  other vias: 2.54,45.72
N$498  (via drill 1.02 pad 1.88)
  other vias: 2.54,48.26
N$499  (via drill 1.02 pad 1.88)
  other vias: 2.54,50.8
N$500  (via drill 1.02 pad 1.88)
  other vias: 7.62,27.94
N$501  (via drill 1.02 pad 1.88)
  other vias: 5.08,25.4
RES
  Top 0.254: JP10.1 31.75,3.81 27.91,3.81 S1.4 22.86,4.39 R3.P$1 24.51,5.46 25.68,6.63 S1.3
RX0
  Top 0.203: JP4.1 63.5,50.8
SCL
  Top 0.203: JP5.1 68.58,50.8 JP5.1
SDA
  Top 0.203: JP5.2 71.12,50.8
TX1
  Top 0.203: JP4.2 60.96,50.8 JP4.2
VIN
  Top 0.203: JP10.6 45.72,2.54 JP10.6

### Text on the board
Bottom: 7/8/09
tPlace: 5V | 9 | 8 | 7 | 6 | 5 | 4 | 3 | 2 | 1 | 0 | 22 | 14 | 15 | 16 | 17 | 18 | 19 | 20 | 21 | 13 | 12 | 11 | 10 | GND | 24 | AREF | PWM | TX | RX | 26 | TX3 | RX3 | TX2 | RX2 | TX1 | RX1 | SDA | SCL | COMMUNICATION | 28 | 5V Bus | 30 | 31 | 32 | 33 | Arduino Mega ProtoShield | 34 | 35 | 36 | 37 | 38 | 39 | 40 | 41 | DIGITAL | 42 | 43 | 44 | 45 | 46 | 47 | 48 | 49 | 50 | 51 | 52 | 53 | GND Bus | ANALOG IN | 0 | 1 | 2 | 3 | 4 | 5 | 6 | 7 | 8 | 9 | 10 | 11 | 12 | 13 | 14 | 15 | GND | RES | 3V3 | 5V | GND | VIN | RESET | STAT | POWER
